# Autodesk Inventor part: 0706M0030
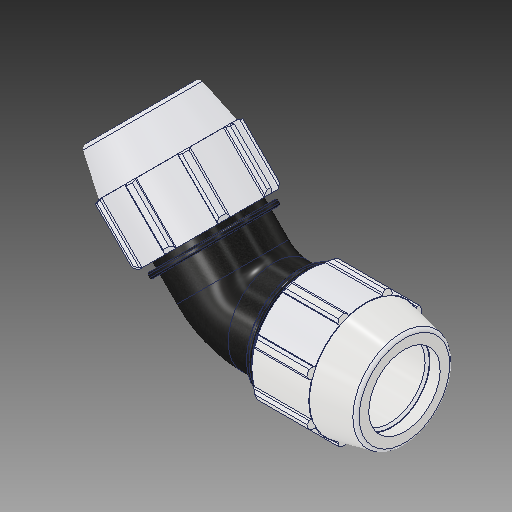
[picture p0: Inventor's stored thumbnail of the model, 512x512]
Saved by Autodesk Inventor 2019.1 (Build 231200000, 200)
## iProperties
Created: 2017-02
Part Number: 0706M0030
Material: PVC-Piping
Description: PLASSON 45° ELBOW 3'' - 3''
Document SubType Name: Modeling
Designer: KIM
Mass: 92.6774 g
Surface Area: 199.44 cm^2
Volume: 66.1981 cm^3
Density: 1.4 g/cm^3
Appearance: PTFE
Author: KIM
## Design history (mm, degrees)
derived "0706M0.ipt"
feature "Solid1::0706M0.ipt"
tag "TaggingFeature1"
body "Solid1"
other parameters: "d2" = 88.7, "d4" = 16.002, "d5" = 48.006, "d7" = 151.892, "d9" = 27.432, "d11" = 6.4008, "d13" = 120 deg, "d14" = 119.745, "d15" = 12 deg, "d16" = 132.14604, "d18" = 4.435, "d19" = 35 deg, "d20" = 17.5 deg, "d21" = 141.25956, "d23" = 0, "d25" = 360 deg, "d27" = 3.03784, "d33" = 1.774, "d42" = 71.04888, "d43" = 4.55676, "d46" = 2.661, "d51" = 192.024, "d59" = 135 deg, "d63" = 162.052, "d67" = 113.919, "d68" = 6.4008, "d72" = 1.5, "d73" = 0, "d74" = 0, "d_" = 88.7, "E_" = 151.892, "A_" = 192.024, "l_" = 162.052
